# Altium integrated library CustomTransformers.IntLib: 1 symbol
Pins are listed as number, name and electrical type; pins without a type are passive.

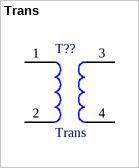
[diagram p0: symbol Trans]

## Trans
designator T??
Transformer TL42S-120-416
footprint Transformer (TL42S-120-416)
pins: 1, 2, 3, 4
